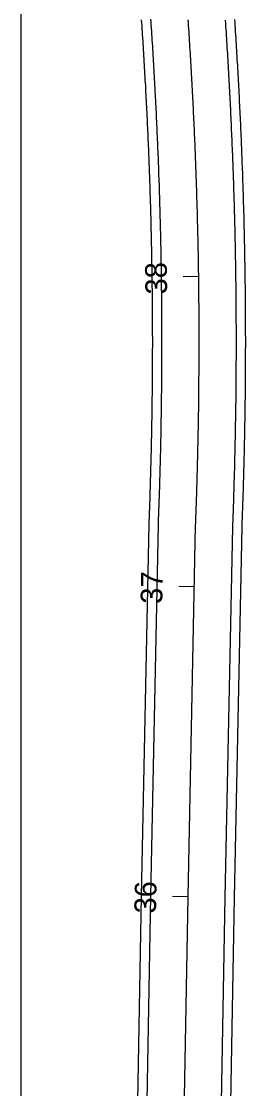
# Model space of a CAD drawing. Extents: x 2318076 to 2324211, y 613525 to 630327.
# Drawn here: x 2318880.5 to 2318952.8, y 618473.2 to 618817.3 of the extents above; entities that cross this region are included whole.
import ezdxf

# ---------------------------------------------------------------- set-up
doc = ezdxf.new("R2010")
doc.units = 0
for name, color, linetype in [('GE_P_CL_50', 7, 'Continuous'), ('PV_P_EOP', 7, 'Continuous'), ('PV_P_Shoulder', 7, 'Continuous'), ('SC_Scratch3', 7, 'Continuous')]:
    doc.layers.add(name, color=color, linetype=linetype)

msp = doc.modelspace()

# ---------------------------------------------------------------- linework, layer by layer
at = {"layer": 'GE_P_CL_50'}
for p, q in [((2318937.67, 618735), (2318932.67, 618734.93)), ((2318936.28, 618635.02), (2318931.28, 618635.12)), ((2318934.25, 618535.04), (2318929.25, 618535.14))]:
    msp.add_line(p, q, dxfattribs=at)
msp.add_lwpolyline([(2318928.83, 618235.09), (2318934.25, 618535.04), (2318936.67, 618654.75), (2318936.71, 618655.73), (2318936.74, 618656.7), (2318936.78, 618657.68), (2318936.82, 618658.66), (2318936.85, 618659.63), (2318936.89, 618660.61), (2318936.92, 618661.58), (2318936.95, 618662.56), (2318936.99, 618663.54), (2318937.02, 618664.51), (2318937.05, 618665.49), (2318937.08, 618666.47), (2318937.11, 618667.44), (2318937.14, 618668.42), (2318937.17, 618669.4), (2318937.2, 618670.37), (2318937.22, 618671.35), (2318937.25, 618672.33), (2318937.28, 618673.3), (2318937.3, 618674.28), (2318937.33, 618675.26), (2318937.35, 618676.23), (2318937.38, 618677.21), (2318937.4, 618678.18), (2318937.42, 618679.16), (2318937.44, 618680.14), (2318937.46, 618681.12), (2318937.48, 618682.09), (2318937.5, 618683.07), (2318937.52, 618684.05), (2318937.54, 618685.02), (2318937.56, 618686), (2318937.58, 618686.98), (2318937.6, 618687.95), (2318937.61, 618688.93), (2318937.63, 618689.91), (2318937.64, 618690.88), (2318937.66, 618691.86), (2318937.67, 618692.84), (2318937.68, 618693.81), (2318937.7, 618694.79), (2318937.71, 618695.77), (2318937.72, 618696.74), (2318937.73, 618697.72), (2318937.74, 618698.7), (2318937.75, 618699.67), (2318937.76, 618700.65), (2318937.79, 618705.54), (2318937.8, 618706.51), (2318937.8, 618707.49), (2318937.81, 618708.47), (2318937.81, 618709.44), (2318937.81, 618710.42), (2318937.81, 618711.4), (2318937.82, 618712.37), (2318937.82, 618713.35), (2318937.82, 618714.33), (2318937.82, 618715.31), (2318937.81, 618716.28), (2318937.81, 618717.26), (2318937.81, 618718.24), (2318937.81, 618719.21), (2318937.8, 618720.19), (2318937.8, 618721.17), (2318937.79, 618722.14), (2318937.79, 618723.12), (2318937.78, 618724.1), (2318937.78, 618725.07), (2318937.77, 618726.05), (2318937.76, 618727.03), (2318937.75, 618728.01), (2318937.74, 618728.98), (2318937.73, 618729.96), (2318937.72, 618730.94), (2318937.71, 618731.91), (2318937.7, 618732.89), (2318937.69, 618733.87), (2318937.67, 618734.84), (2318937.66, 618735.82), (2318937.65, 618736.8), (2318937.63, 618737.77), (2318937.61, 618738.75), (2318937.6, 618739.73), (2318937.58, 618740.7), (2318937.56, 618741.68), (2318937.55, 618742.66), (2318937.53, 618743.63), (2318937.51, 618744.61), (2318937.49, 618745.59), (2318937.47, 618746.56), (2318937.45, 618747.54), (2318937.42, 618748.52), (2318937.4, 618749.49), (2318937.38, 618750.47), (2318937.36, 618751.45), (2318937.33, 618752.42), (2318937.31, 618753.4), (2318937.28, 618754.38), (2318937.25, 618755.35), (2318937.23, 618756.33), (2318937.2, 618757.31), (2318937.17, 618758.28), (2318937.14, 618759.26), (2318937.11, 618760.24), (2318937.08, 618761.21), (2318937.05, 618762.19), (2318937.02, 618763.17), (2318936.99, 618764.14), (2318936.96, 618765.12), (2318936.93, 618766.1), (2318936.89, 618767.07), (2318936.86, 618768.05), (2318936.82, 618769.02), (2318936.79, 618770), (2318936.75, 618770.98), (2318936.71, 618771.95), (2318936.68, 618772.93), (2318936.64, 618773.91), (2318936.6, 618774.88), (2318936.56, 618775.86), (2318936.52, 618776.83), (2318936.48, 618777.81), (2318936.44, 618778.79), (2318936.4, 618779.76), (2318936.35, 618780.74), (2318936.31, 618781.71), (2318936.27, 618782.69), (2318936.22, 618783.67), (2318936.18, 618784.64), (2318936.13, 618785.62), (2318936.09, 618786.59), (2318936.04, 618787.57), (2318935.99, 618788.54), (2318935.94, 618789.52), (2318935.9, 618790.5), (2318935.85, 618791.47), (2318935.8, 618792.45), (2318935.75, 618793.42), (2318935.7, 618794.4), (2318935.64, 618795.37), (2318935.59, 618796.35), (2318935.54, 618797.33), (2318935.48, 618798.3), (2318935.43, 618799.28), (2318935.38, 618800.25), (2318935.32, 618801.23), (2318935.26, 618802.2), (2318935.21, 618803.18), (2318935.15, 618804.15), (2318935.09, 618805.13), (2318935.03, 618806.1), (2318934.97, 618807.08), (2318934.91, 618808.05), (2318934.85, 618809.03), (2318934.79, 618810), (2318934.73, 618810.98), (2318934.67, 618811.95), (2318934.61, 618812.93), (2318934.54, 618813.9), (2318934.48, 618814.88), (2318934.41, 618815.85), (2318934.35, 618816.83), (2318934.28, 618817.8)], dxfattribs=at)
at = {"layer": 'PV_P_EOP'}
for points in [[(2318916.83, 618235.27), (2318922.25, 618535.27), (2318924.67, 618655.1), (2318924.72, 618656.18), (2318924.75, 618657.15), (2318924.79, 618658.12), (2318924.82, 618659.09), (2318924.86, 618660.06), (2318924.89, 618661.03), (2318924.93, 618662), (2318924.96, 618662.96), (2318924.99, 618663.93), (2318925.02, 618664.9), (2318925.05, 618665.87), (2318925.08, 618666.84), (2318925.11, 618667.81), (2318925.14, 618668.78), (2318925.17, 618669.75), (2318925.2, 618670.71), (2318925.23, 618671.68), (2318925.25, 618672.65), (2318925.28, 618673.62), (2318925.31, 618674.59), (2318925.33, 618675.56), (2318925.36, 618676.53), (2318925.38, 618677.5), (2318925.4, 618678.47), (2318925.42, 618679.43), (2318925.45, 618680.4), (2318925.47, 618681.37), (2318925.49, 618682.34), (2318925.51, 618683.31), (2318925.53, 618684.28), (2318925.55, 618685.25), (2318925.56, 618686.22), (2318925.58, 618687.19), (2318925.6, 618688.16), (2318925.61, 618689.13), (2318925.63, 618690.09), (2318925.64, 618691.06), (2318925.66, 618692.03), (2318925.67, 618693), (2318925.69, 618693.97), (2318925.7, 618694.94), (2318925.71, 618695.91), (2318925.72, 618696.88), (2318925.73, 618697.85), (2318925.74, 618698.82), (2318925.75, 618699.79), (2318925.76, 618700.75), (2318925.79, 618705.61), (2318925.8, 618706.57), (2318925.8, 618707.54), (2318925.81, 618708.51), (2318925.81, 618709.48), (2318925.81, 618710.45), (2318925.81, 618711.42), (2318925.82, 618712.39), (2318925.82, 618713.36), (2318925.82, 618714.33), (2318925.82, 618715.29), (2318925.81, 618716.26), (2318925.81, 618717.23), (2318925.81, 618718.2), (2318925.81, 618719.17), (2318925.8, 618720.14), (2318925.8, 618721.11), (2318925.79, 618722.08), (2318925.79, 618723.05), (2318925.78, 618724.02), (2318925.78, 618724.99), (2318925.77, 618725.96), (2318925.76, 618726.93), (2318925.75, 618727.89), (2318925.74, 618728.86), (2318925.73, 618729.83), (2318925.72, 618730.8), (2318925.71, 618731.77), (2318925.7, 618732.74), (2318925.69, 618733.71), (2318925.67, 618734.68), (2318925.66, 618735.65), (2318925.65, 618736.62), (2318925.63, 618737.59), (2318925.62, 618738.56), (2318925.6, 618739.52), (2318925.58, 618740.49), (2318925.57, 618741.46), (2318925.55, 618742.43), (2318925.53, 618743.4), (2318925.51, 618744.37), (2318925.49, 618745.34), (2318925.47, 618746.31), (2318925.45, 618747.28), (2318925.43, 618748.25), (2318925.41, 618749.22), (2318925.38, 618750.18), (2318925.36, 618751.15), (2318925.33, 618752.12), (2318925.31, 618753.09), (2318925.28, 618754.06), (2318925.26, 618755.03), (2318925.23, 618756), (2318925.21, 618756.97), (2318925.18, 618757.94), (2318925.15, 618758.9), (2318925.12, 618759.87), (2318925.09, 618760.84), (2318925.06, 618761.81), (2318925.03, 618762.78), (2318925, 618763.75), (2318924.97, 618764.72), (2318924.93, 618765.69), (2318924.9, 618766.65), (2318924.86, 618767.62), (2318924.83, 618768.59), (2318924.79, 618769.56), (2318924.76, 618770.53), (2318924.72, 618771.5), (2318924.69, 618772.47), (2318924.65, 618773.43), (2318924.61, 618774.4), (2318924.57, 618775.37), (2318924.53, 618776.34), (2318924.49, 618777.31), (2318924.45, 618778.28), (2318924.41, 618779.24), (2318924.37, 618780.21), (2318924.32, 618781.18), (2318924.28, 618782.15), (2318924.24, 618783.12), (2318924.19, 618784.09), (2318924.15, 618785.05), (2318924.1, 618786.02), (2318924.05, 618786.99), (2318924.01, 618787.96), (2318923.96, 618788.93), (2318923.91, 618789.89), (2318923.86, 618790.86), (2318923.81, 618791.83), (2318923.76, 618792.8), (2318923.71, 618793.77), (2318923.66, 618794.73), (2318923.61, 618795.7), (2318923.56, 618796.67), (2318923.5, 618797.64), (2318923.45, 618798.61), (2318923.39, 618799.57), (2318923.34, 618800.54), (2318923.28, 618801.51), (2318923.23, 618802.48), (2318923.17, 618803.44), (2318923.11, 618804.41), (2318923.05, 618805.38), (2318923, 618806.35), (2318922.94, 618807.31), (2318922.88, 618808.28), (2318922.82, 618809.25), (2318922.75, 618810.22), (2318922.69, 618811.18), (2318922.63, 618812.15), (2318922.57, 618813.12), (2318922.5, 618814.08), (2318922.44, 618815.05), (2318922.37, 618816.02), (2318922.31, 618816.99), (2318922.24, 618817.95)], [(2318940.83, 618234.92), (2318946.25, 618534.81), (2318948.67, 618654.4), (2318948.7, 618655.27), (2318948.74, 618656.25), (2318948.77, 618657.24), (2318948.81, 618658.22), (2318948.84, 618659.2), (2318948.88, 618660.19), (2318948.91, 618661.17), (2318948.95, 618662.16), (2318948.98, 618663.14), (2318949.01, 618664.13), (2318949.04, 618665.11), (2318949.07, 618666.09), (2318949.1, 618667.08), (2318949.13, 618668.06), (2318949.16, 618669.05), (2318949.19, 618670.03), (2318949.22, 618671.01), (2318949.25, 618672), (2318949.27, 618672.98), (2318949.3, 618673.97), (2318949.32, 618674.95), (2318949.35, 618675.94), (2318949.37, 618676.92), (2318949.4, 618677.9), (2318949.42, 618678.89), (2318949.44, 618679.87), (2318949.46, 618680.86), (2318949.48, 618681.84), (2318949.5, 618682.83), (2318949.52, 618683.81), (2318949.54, 618684.79), (2318949.56, 618685.78), (2318949.58, 618686.76), (2318949.59, 618687.75), (2318949.61, 618688.73), (2318949.63, 618689.72), (2318949.64, 618690.7), (2318949.66, 618691.69), (2318949.67, 618692.67), (2318949.68, 618693.66), (2318949.7, 618694.64), (2318949.71, 618695.62), (2318949.72, 618696.61), (2318949.73, 618697.59), (2318949.74, 618698.58), (2318949.75, 618699.56), (2318949.76, 618700.55), (2318949.79, 618705.46), (2318949.8, 618706.45), (2318949.8, 618707.44), (2318949.81, 618708.42), (2318949.81, 618709.41), (2318949.81, 618710.39), (2318949.81, 618711.38), (2318949.82, 618712.36), (2318949.82, 618713.35), (2318949.82, 618714.33), (2318949.82, 618715.32), (2318949.81, 618716.3), (2318949.81, 618717.29), (2318949.81, 618718.27), (2318949.81, 618719.25), (2318949.8, 618720.24), (2318949.8, 618721.22), (2318949.79, 618722.21), (2318949.79, 618723.19), (2318949.78, 618724.18), (2318949.78, 618725.16), (2318949.77, 618726.15), (2318949.76, 618727.13), (2318949.75, 618728.12), (2318949.74, 618729.1), (2318949.73, 618730.08), (2318949.72, 618731.07), (2318949.71, 618732.05), (2318949.7, 618733.04), (2318949.69, 618734.02), (2318949.67, 618735.01), (2318949.66, 618735.99), (2318949.64, 618736.98), (2318949.63, 618737.96), (2318949.61, 618738.95), (2318949.6, 618739.93), (2318949.58, 618740.91), (2318949.56, 618741.9), (2318949.54, 618742.88), (2318949.53, 618743.87), (2318949.51, 618744.85), (2318949.49, 618745.84), (2318949.46, 618746.82), (2318949.44, 618747.81), (2318949.42, 618748.79), (2318949.4, 618749.77), (2318949.38, 618750.76), (2318949.35, 618751.74), (2318949.33, 618752.73), (2318949.3, 618753.71), (2318949.28, 618754.7), (2318949.25, 618755.68), (2318949.22, 618756.66), (2318949.2, 618757.65), (2318949.17, 618758.63), (2318949.14, 618759.62), (2318949.11, 618760.6), (2318949.08, 618761.58), (2318949.05, 618762.57), (2318949.02, 618763.55), (2318948.98, 618764.54), (2318948.95, 618765.52), (2318948.92, 618766.51), (2318948.88, 618767.49), (2318948.85, 618768.47), (2318948.81, 618769.46), (2318948.78, 618770.44), (2318948.74, 618771.42), (2318948.71, 618772.41), (2318948.67, 618773.39), (2318948.63, 618774.38), (2318948.59, 618775.36), (2318948.55, 618776.34), (2318948.51, 618777.33), (2318948.47, 618778.31), (2318948.43, 618779.3), (2318948.39, 618780.28), (2318948.34, 618781.26), (2318948.3, 618782.25), (2318948.26, 618783.23), (2318948.21, 618784.21), (2318948.17, 618785.2), (2318948.12, 618786.18), (2318948.07, 618787.16), (2318948.03, 618788.15), (2318947.98, 618789.13), (2318947.93, 618790.11), (2318947.88, 618791.1), (2318947.83, 618792.08), (2318947.78, 618793.06), (2318947.73, 618794.05), (2318947.68, 618795.03), (2318947.63, 618796.01), (2318947.57, 618797), (2318947.52, 618797.98), (2318947.47, 618798.96), (2318947.41, 618799.95), (2318947.36, 618800.93), (2318947.3, 618801.91), (2318947.24, 618802.9), (2318947.19, 618803.88), (2318947.13, 618804.86), (2318947.07, 618805.84), (2318947.01, 618806.83), (2318946.95, 618807.81), (2318946.89, 618808.79), (2318946.83, 618809.78), (2318946.77, 618810.76), (2318946.71, 618811.74), (2318946.64, 618812.72), (2318946.58, 618813.71), (2318946.52, 618814.69), (2318946.45, 618815.67), (2318946.39, 618816.65), (2318946.32, 618817.64)]]:
    msp.add_lwpolyline(points, dxfattribs=at)
at = {"layer": 'PV_P_Shoulder'}
for points in [[(2318913.83, 618235.32), (2318919.25, 618535.32), (2318921.68, 618655.19), (2318921.72, 618656.3), (2318921.75, 618657.26), (2318921.79, 618658.23), (2318921.83, 618659.2), (2318921.86, 618660.16), (2318921.89, 618661.13), (2318921.93, 618662.1), (2318921.96, 618663.06), (2318921.99, 618664.03), (2318922.03, 618665), (2318922.06, 618665.97), (2318922.09, 618666.93), (2318922.12, 618667.9), (2318922.15, 618668.87), (2318922.17, 618669.83), (2318922.2, 618670.8), (2318922.23, 618671.77), (2318922.26, 618672.73), (2318922.28, 618673.7), (2318922.31, 618674.67), (2318922.33, 618675.63), (2318922.36, 618676.6), (2318922.38, 618677.57), (2318922.4, 618678.54), (2318922.42, 618679.5), (2318922.45, 618680.47), (2318922.47, 618681.44), (2318922.49, 618682.4), (2318922.51, 618683.37), (2318922.53, 618684.34), (2318922.55, 618685.31), (2318922.56, 618686.27), (2318922.58, 618687.24), (2318922.6, 618688.21), (2318922.61, 618689.17), (2318922.63, 618690.14), (2318922.64, 618691.11), (2318922.66, 618692.08), (2318922.67, 618693.04), (2318922.69, 618694.01), (2318922.7, 618694.98), (2318922.71, 618695.95), (2318922.72, 618696.91), (2318922.73, 618697.88), (2318922.74, 618698.85), (2318922.75, 618699.81), (2318922.76, 618700.77), (2318922.79, 618705.63), (2318922.8, 618706.59), (2318922.8, 618707.55), (2318922.81, 618708.52), (2318922.81, 618709.49), (2318922.81, 618710.45), (2318922.81, 618711.42), (2318922.82, 618712.39), (2318922.82, 618713.36), (2318922.82, 618714.32), (2318922.82, 618715.29), (2318922.81, 618716.26), (2318922.81, 618717.23), (2318922.81, 618718.19), (2318922.81, 618719.16), (2318922.8, 618720.13), (2318922.8, 618721.1), (2318922.79, 618722.06), (2318922.79, 618723.03), (2318922.78, 618724), (2318922.78, 618724.96), (2318922.77, 618725.93), (2318922.76, 618726.9), (2318922.75, 618727.87), (2318922.74, 618728.83), (2318922.73, 618729.8), (2318922.72, 618730.77), (2318922.71, 618731.74), (2318922.7, 618732.7), (2318922.69, 618733.67), (2318922.67, 618734.64), (2318922.66, 618735.6), (2318922.65, 618736.57), (2318922.63, 618737.54), (2318922.62, 618738.51), (2318922.6, 618739.47), (2318922.58, 618740.44), (2318922.57, 618741.41), (2318922.55, 618742.38), (2318922.53, 618743.34), (2318922.51, 618744.31), (2318922.49, 618745.28), (2318922.47, 618746.24), (2318922.45, 618747.21), (2318922.43, 618748.18), (2318922.41, 618749.15), (2318922.38, 618750.11), (2318922.36, 618751.08), (2318922.34, 618752.05), (2318922.31, 618753.01), (2318922.29, 618753.98), (2318922.26, 618754.95), (2318922.23, 618755.91), (2318922.21, 618756.88), (2318922.18, 618757.85), (2318922.15, 618758.82), (2318922.12, 618759.78), (2318922.09, 618760.75), (2318922.06, 618761.72), (2318922.03, 618762.68), (2318922, 618763.65), (2318921.97, 618764.62), (2318921.93, 618765.58), (2318921.9, 618766.55), (2318921.87, 618767.52), (2318921.83, 618768.48), (2318921.8, 618769.45), (2318921.76, 618770.42), (2318921.72, 618771.38), (2318921.69, 618772.35), (2318921.65, 618773.32), (2318921.61, 618774.28), (2318921.57, 618775.25), (2318921.53, 618776.22), (2318921.49, 618777.18), (2318921.45, 618778.15), (2318921.41, 618779.12), (2318921.37, 618780.08), (2318921.33, 618781.05), (2318921.28, 618782.01), (2318921.24, 618782.98), (2318921.19, 618783.95), (2318921.15, 618784.91), (2318921.1, 618785.88), (2318921.06, 618786.85), (2318921.01, 618787.81), (2318920.96, 618788.78), (2318920.92, 618789.74), (2318920.87, 618790.71), (2318920.82, 618791.68), (2318920.77, 618792.64), (2318920.72, 618793.61), (2318920.66, 618794.57), (2318920.61, 618795.54), (2318920.56, 618796.51), (2318920.51, 618797.47), (2318920.45, 618798.44), (2318920.4, 618799.4), (2318920.34, 618800.37), (2318920.29, 618801.34), (2318920.23, 618802.3), (2318920.18, 618803.27), (2318920.12, 618804.23), (2318920.06, 618805.2), (2318920, 618806.16), (2318919.94, 618807.13), (2318919.88, 618808.09), (2318919.82, 618809.06), (2318919.76, 618810.03), (2318919.7, 618810.99), (2318919.64, 618811.96), (2318919.57, 618812.92), (2318919.51, 618813.89), (2318919.45, 618814.85), (2318919.38, 618815.82), (2318919.32, 618816.78), (2318919.25, 618817.75)], [(2318943.83, 618234.87), (2318949.25, 618534.75), (2318951.66, 618654.31), (2318951.7, 618655.15), (2318951.73, 618656.14), (2318951.77, 618657.13), (2318951.81, 618658.11), (2318951.84, 618659.1), (2318951.88, 618660.08), (2318951.91, 618661.07), (2318951.94, 618662.06), (2318951.98, 618663.04), (2318952.01, 618664.03), (2318952.04, 618665.01), (2318952.07, 618666), (2318952.1, 618666.99), (2318952.13, 618667.97), (2318952.16, 618668.96), (2318952.19, 618669.94), (2318952.22, 618670.93), (2318952.24, 618671.92), (2318952.27, 618672.9), (2318952.3, 618673.89), (2318952.32, 618674.88), (2318952.35, 618675.86), (2318952.37, 618676.85), (2318952.39, 618677.83), (2318952.42, 618678.82), (2318952.44, 618679.81), (2318952.46, 618680.79), (2318952.48, 618681.78), (2318952.5, 618682.77), (2318952.52, 618683.75), (2318952.54, 618684.74), (2318952.56, 618685.72), (2318952.58, 618686.71), (2318952.59, 618687.7), (2318952.61, 618688.68), (2318952.63, 618689.67), (2318952.64, 618690.66), (2318952.66, 618691.64), (2318952.67, 618692.63), (2318952.68, 618693.62), (2318952.7, 618694.6), (2318952.71, 618695.59), (2318952.72, 618696.58), (2318952.73, 618697.56), (2318952.74, 618698.55), (2318952.75, 618699.53), (2318952.76, 618700.53), (2318952.79, 618705.44), (2318952.8, 618706.44), (2318952.8, 618707.43), (2318952.81, 618708.41), (2318952.81, 618709.4), (2318952.81, 618710.39), (2318952.81, 618711.37), (2318952.82, 618712.36), (2318952.82, 618713.35), (2318952.82, 618714.33), (2318952.82, 618715.32), (2318952.81, 618716.31), (2318952.81, 618717.29), (2318952.81, 618718.28), (2318952.81, 618719.26), (2318952.8, 618720.25), (2318952.8, 618721.24), (2318952.79, 618722.22), (2318952.79, 618723.21), (2318952.78, 618724.2), (2318952.78, 618725.18), (2318952.77, 618726.17), (2318952.76, 618727.16), (2318952.75, 618728.14), (2318952.74, 618729.13), (2318952.73, 618730.12), (2318952.72, 618731.1), (2318952.71, 618732.09), (2318952.7, 618733.08), (2318952.68, 618734.06), (2318952.67, 618735.05), (2318952.66, 618736.03), (2318952.64, 618737.02), (2318952.63, 618738.01), (2318952.61, 618738.99), (2318952.6, 618739.98), (2318952.58, 618740.97), (2318952.56, 618741.95), (2318952.54, 618742.94), (2318952.52, 618743.93), (2318952.51, 618744.91), (2318952.48, 618745.9), (2318952.46, 618746.88), (2318952.44, 618747.87), (2318952.42, 618748.86), (2318952.4, 618749.84), (2318952.37, 618750.83), (2318952.35, 618751.82), (2318952.33, 618752.8), (2318952.3, 618753.79), (2318952.28, 618754.77), (2318952.25, 618755.76), (2318952.22, 618756.75), (2318952.19, 618757.73), (2318952.17, 618758.72), (2318952.14, 618759.71), (2318952.11, 618760.69), (2318952.08, 618761.68), (2318952.05, 618762.66), (2318952.01, 618763.65), (2318951.98, 618764.64), (2318951.95, 618765.62), (2318951.92, 618766.61), (2318951.88, 618767.59), (2318951.85, 618768.58), (2318951.81, 618769.57), (2318951.78, 618770.55), (2318951.74, 618771.54), (2318951.7, 618772.52), (2318951.67, 618773.51), (2318951.63, 618774.49), (2318951.59, 618775.48), (2318951.55, 618776.47), (2318951.51, 618777.45), (2318951.47, 618778.44), (2318951.43, 618779.42), (2318951.38, 618780.41), (2318951.34, 618781.39), (2318951.3, 618782.38), (2318951.25, 618783.36), (2318951.21, 618784.35), (2318951.16, 618785.34), (2318951.12, 618786.32), (2318951.07, 618787.31), (2318951.02, 618788.29), (2318950.97, 618789.28), (2318950.93, 618790.26), (2318950.88, 618791.25), (2318950.83, 618792.23), (2318950.78, 618793.22), (2318950.73, 618794.2), (2318950.67, 618795.19), (2318950.62, 618796.17), (2318950.57, 618797.16), (2318950.52, 618798.14), (2318950.46, 618799.13), (2318950.41, 618800.11), (2318950.35, 618801.1), (2318950.3, 618802.08), (2318950.24, 618803.07), (2318950.18, 618804.05), (2318950.12, 618805.04), (2318950.06, 618806.02), (2318950.01, 618807.01), (2318949.95, 618807.99), (2318949.89, 618808.98), (2318949.82, 618809.96), (2318949.76, 618810.95), (2318949.7, 618811.93), (2318949.64, 618812.92), (2318949.57, 618813.9), (2318949.51, 618814.88), (2318949.44, 618815.87), (2318949.38, 618816.85), (2318949.31, 618817.84)]]:
    msp.add_lwpolyline(points, dxfattribs=at)
at = {"layer": 'SC_Scratch3'}
msp.add_line((2318880.45, 614778.41), (2318880.45, 630327.22), dxfattribs=at)

# ---------------------------------------------------------------- texts
at = {"layer": 'GE_P_CL_50'}
for s, rotation, p in [('38', 90.8029, (2318927.5, 618729.31)), ('37', 88.8653, (2318925.91, 618629.47)), ('36', 88.7923, (2318923.88, 618529.65))]:
    msp.add_text(s, height=7, rotation=rotation, dxfattribs=at).set_placement(p)

doc.saveas('drawing.dxf')
